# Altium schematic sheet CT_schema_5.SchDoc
size 422 x 246 mm
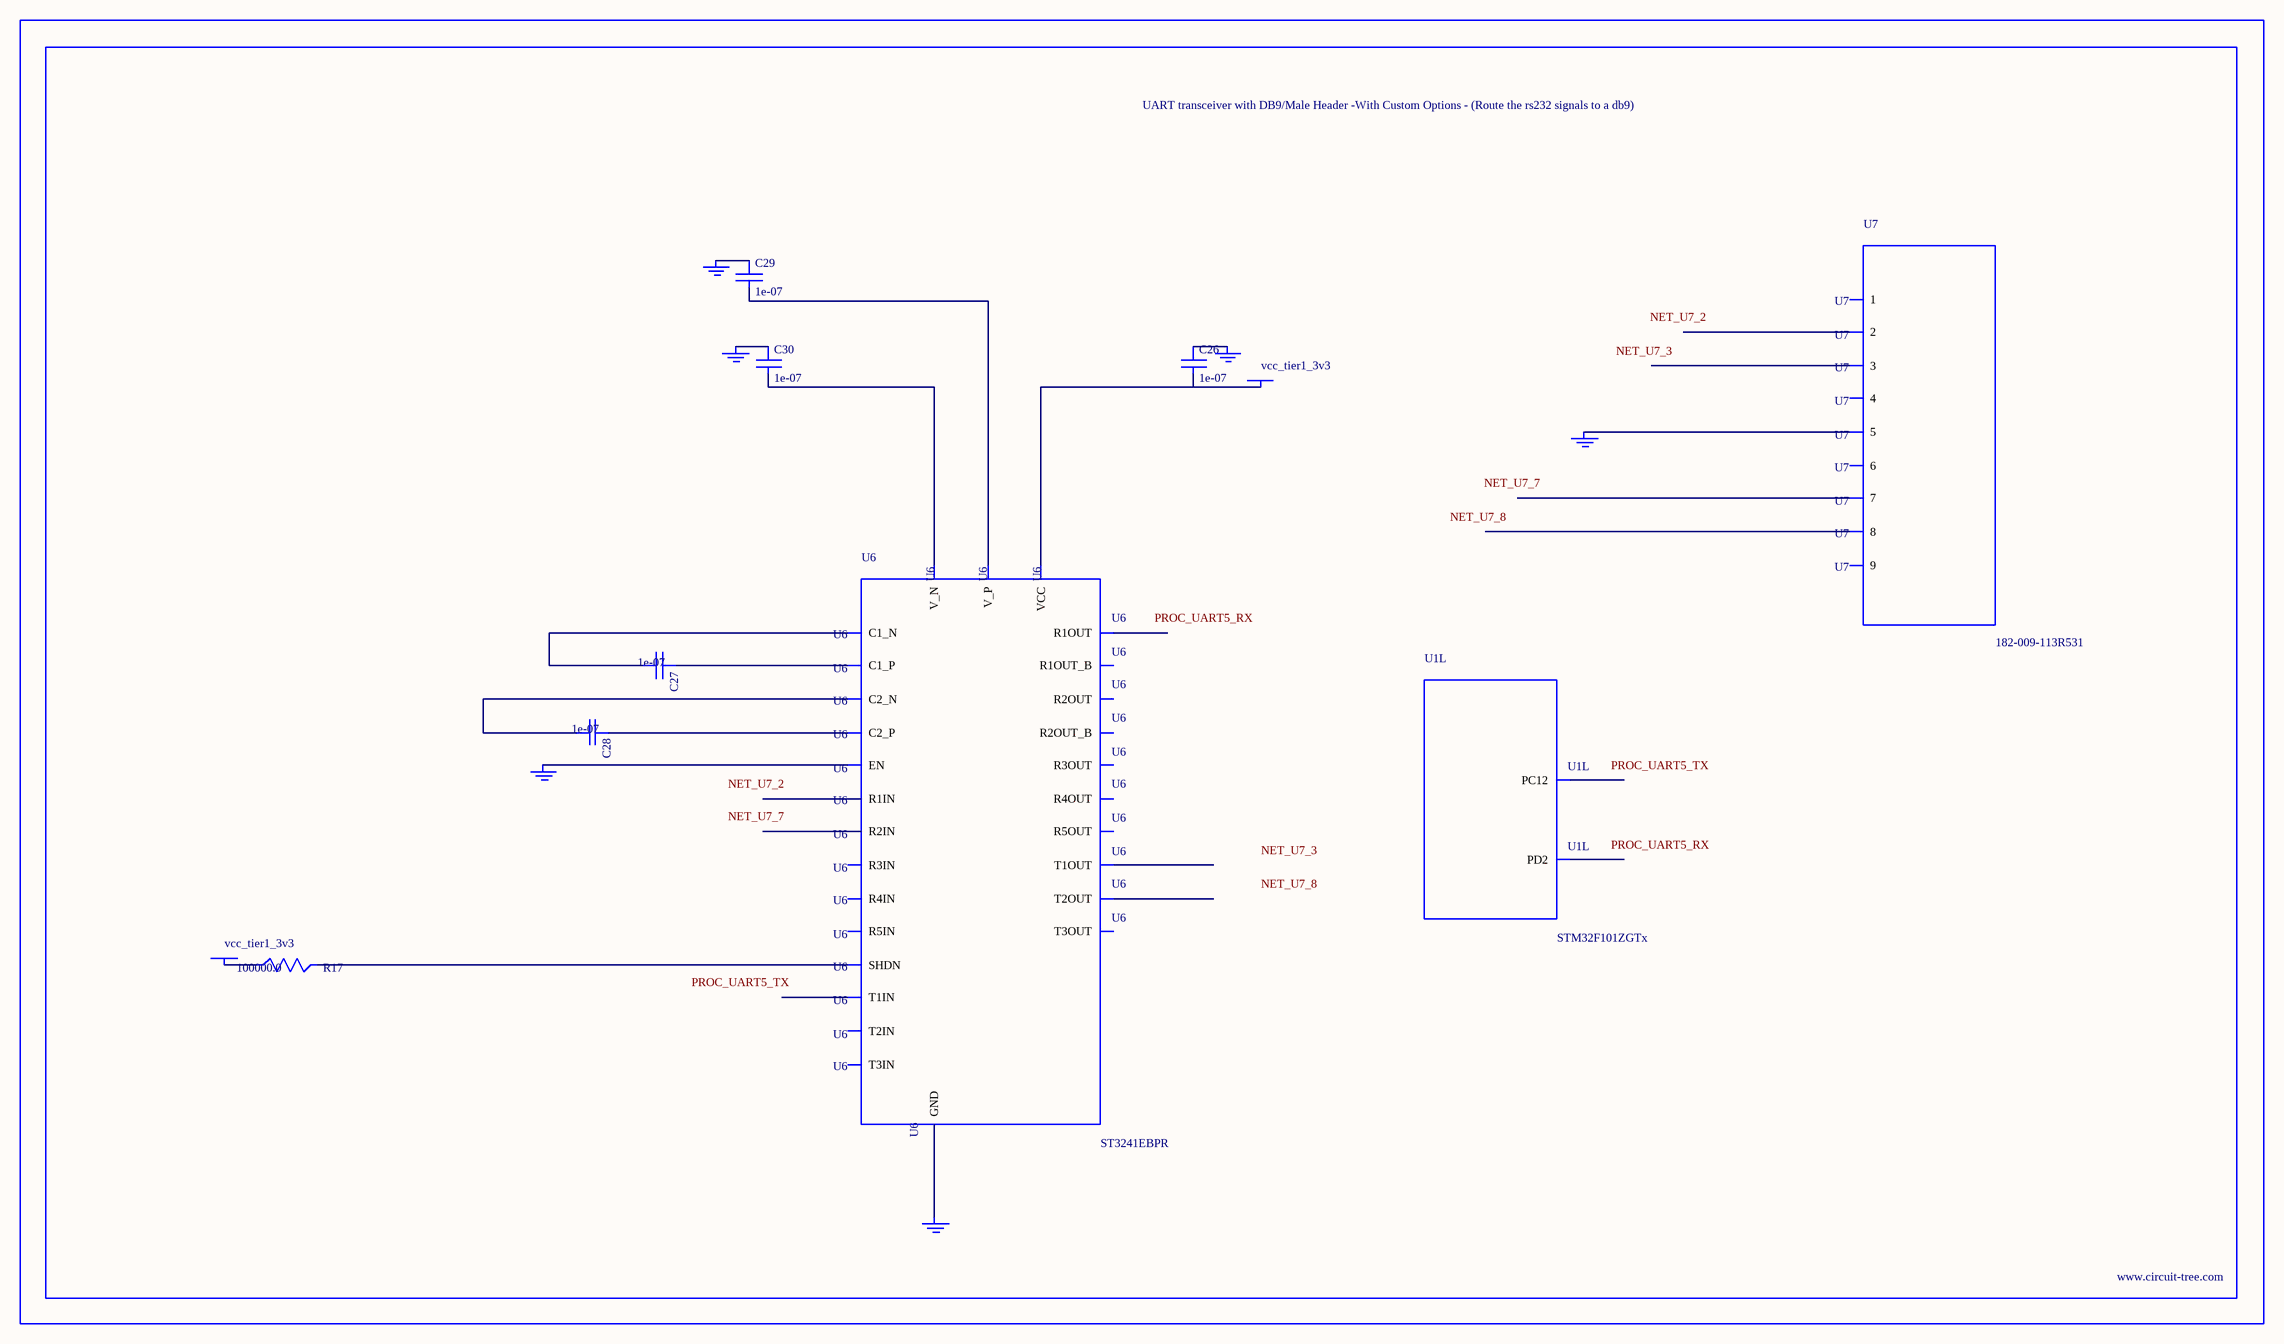
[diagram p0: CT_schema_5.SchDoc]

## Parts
BORDER4  (no value)
C26  1e-07  [C0402]
C27  1e-07  [C0402]
C28  1e-07  [C0402]
C29  1e-07  [C0402]
C30  1e-07  [C0402]
GND_INSTANCE_4_0  (no value)
GND_INSTANCE_4_1  (no value)
GND_INSTANCE_4_2  (no value)
GND_INSTANCE_4_3  (no value)
GND_INSTANCE_4_4  (no value)
GND_INSTANCE_4_5  (no value)
POWER_INSTANCE_4_0  vcc_tier1_3v3
POWER_INSTANCE_4_1  vcc_tier1_3v3
R17  100000.0  [R0603]
U1  STM32F101ZGTx  [LQFP144]  (part L of 13)
U6  ST3241EBPR  [SSOP-28]
U7  182-009-113R531  [182-009-MALE]

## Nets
NetC26_1: C26.1 GND_INSTANCE_4_2.0(GND)
NetC26_2: C26.2 POWER_INSTANCE_4_1.0(PWR) U6.26(VCC)
NetC27_1: C27.1 U6.28(C1_P)
NetC27_2: C27.2 U6.24(C1_N)
NetC28_1: C28.1 U6.1(C2_P)
NetC28_2: C28.2 U6.2(C2_N)
NetC29_1: C29.1 GND_INSTANCE_4_3.0(GND)
NetC29_2: C29.2 U6.27(V_P)
NetC30_1: C30.1 GND_INSTANCE_4_0.0(GND)
NetC30_2: C30.2 U6.3(V_N)
NetGND_INSTANCE_4_1_0: GND_INSTANCE_4_1.0(GND) U6.23(EN)
NetGND_INSTANCE_4_4_0: GND_INSTANCE_4_4.0(GND) U6.25(GND)
NetGND_INSTANCE_4_5_0: GND_INSTANCE_4_5.0(GND) U7.5
NetPOWER_INSTANCE_4_0_0: POWER_INSTANCE_4_0.0(PWR) R17.1
NetR17_2: R17.2 U6.22(SHDN)

Not connected (* = marked no-connect by the designer): U1 113(PC12) 116(PD2); U6 4(R1IN) 5(R2IN) 6(R3IN) 7(R4IN) 8(R5IN) 9(T1OUT) 10(T2OUT) 11(T3OUT) 12(T3IN) 13(T2IN) 14(T1IN) 15(R5OUT) 16(R4OUT) 17(R3OUT) 18(R2OUT) 19(R1OUT) 20(R2OUT_B) 21(R1OUT_B); U7 1 2 3 4 6 7 8 9

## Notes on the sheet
- Labels drawn without touching a wire or pin: NET_U7_2, NET_U7_3, NET_U7_7, NET_U7_8, PROC_UART5_RX, PROC_UART5_TX

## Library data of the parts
BORDER4 = BORDER_PAGE4
C26-C30 = C0402C104K3RACTU
GND_INSTANCE_4_0-GND_INSTANCE_4_5 = GND
POWER_INSTANCE_4_0 POWER_INSTANCE_4_1 = PWR
R17 = RC0603JR-07100KL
